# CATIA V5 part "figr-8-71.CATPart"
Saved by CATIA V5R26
Part number: Part1
Bounding box of the stored display mesh (mm): x -81.893 to 81.893, y -175.508 to 175.508, z -150 to 146
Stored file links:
  D:\_Deepak\CATIA\CATIA V5-6R2016_Deepak\Resources\Part files\Partfiles\c08_catia_v5_6r2016_prt\figr-8-71.CATPart
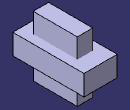
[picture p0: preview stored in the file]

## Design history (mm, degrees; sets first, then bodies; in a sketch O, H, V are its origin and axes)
Body1 (main body)
  Sketch1 on xy-plane, origin (0, 0, 0), H (1, 0, 0), V (0, 1, 0)
    line L1 (-81.8929, 175.5076) -> (81.8929, 175.5076)
    line L2 (81.8929, 175.5076) -> (81.8929, -175.5076)
    line L3 (81.8929, -175.5076) -> (-81.8929, -175.5076)
    line L4 (-81.8929, -175.5076) -> (-81.8929, 175.5076)
    axis line L5 (81.8929, -175.5076) -> (-81.8929, 175.5076)
    horizontal: L1 H, L3 H
    vertical: L2 V, L4 V
    midpoint: O L5
  Pad1: profile Sketch1, direction (0, 0, 1), length 50, mirrored extent
Body2
  Sketch2 on xy-plane, origin (0, 0, 0), H (1, 0, 0), V (0, 1, 0)
    line L1 (-37.4906, 99.3013) -> (38.4681, 99.3013)
    line L2 (38.4681, 99.3013) -> (38.4681, -118.5305)
    line L3 (38.4681, -118.5305) -> (-37.4906, -118.5305)
    line L4 (-37.4906, -118.5305) -> (-37.4906, 99.3013)
    horizontal: L1 H, L3 H
    vertical: L2 V, L4 V
  Pad2: profile Sketch2, direction (0, 0, 1), length 146, opposite side length 150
